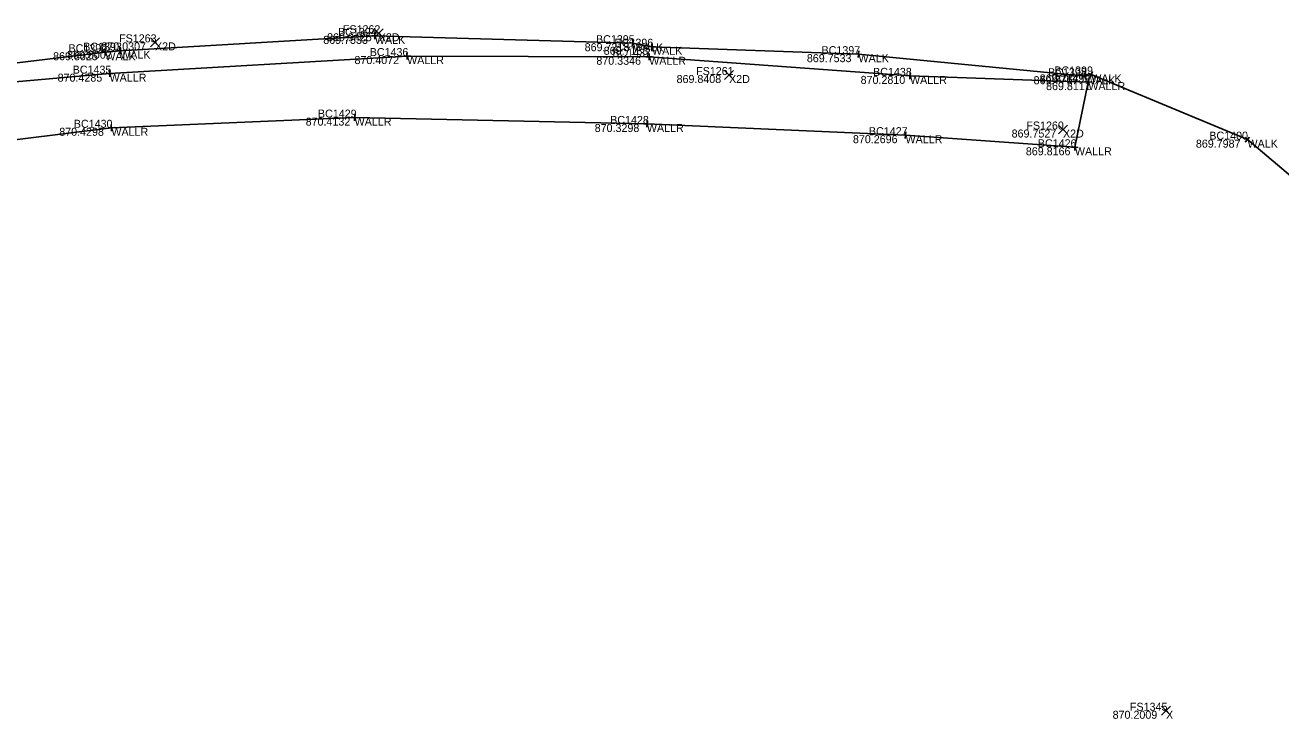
# Model space of a CAD drawing. Extents: x 1479425 to 1480294, y 379351 to 380102.
# Drawn here: x 1479629.1 to 1479638.52, y 379868.14 to 379873.34 of the extents above; entities that cross this region are included whole.
import ezdxf

# ---------------------------------------------------------------- set-up
doc = ezdxf.new("R2010")
doc.units = 0
for name, color, linetype in [('PV_X_Walk', 7, 'Continuous'), ('RD_X_Wall', 7, 'Continuous'), ('SV_X_Random_Point', 7, 'Continuous'), ('SV_X_Shot_Marker', 7, 'Continuous'), ('SV_X_Text_Comment', 7, 'Continuous'), ('SV_X_Text_Elevation', 7, 'Continuous'), ('SV_X_Text_Name', 7, 'Continuous')]:
    doc.layers.add(name, color=color, linetype=linetype)

msp = doc.modelspace()

# ---------------------------------------------------------------- linework, layer by layer
at = {"layer": 'PV_X_Walk'}
msp.add_lwpolyline([(1479639.0409, 379871.8337), (1479638.2687, 379872.4839), (1479637.0974, 379872.9725), (1479637.0508, 379872.9593), (1479635.3514, 379873.1245), (1479633.8033, 379873.1802), (1479633.6601, 379873.2067), (1479631.7248, 379873.2616), (1479629.8147, 379873.1506), (1479629.7038, 379873.1391), (1479627.9217, 379872.925), (1479625.77, 379872.5683), (1479625.6217, 379872.6102), (1479623.1104, 379872.0351)], dxfattribs=at)
at = {"layer": 'RD_X_Wall'}
msp.add_lwpolyline([(1479636.9747, 379872.4267), (1479635.7044, 379872.5174), (1479633.7647, 379872.6014), (1479631.5731, 379872.6491), (1479629.7491, 379872.5728), (1479626.9881, 379872.2291), (1479625.7759, 379872.0832), (1479625.7496, 379872.5499), (1479627.327, 379872.7681), (1479629.7353, 379872.9786), (1479631.9666, 379873.1104), (1479633.7819, 379873.105), (1479635.738, 379872.9618), (1479637.0752, 379872.9151)], close=True, dxfattribs=at)
at = {"layer": 'SV_X_Random_Point'}
for p, q in [((1479631.7207, 379873.2479), (1479631.7873, 379873.3147)), ((1479631.7207, 379873.3147), (1479631.7873, 379873.2479)), ((1479630.0427, 379873.1797), (1479630.1093, 379873.2465)), ((1479630.0427, 379873.2465), (1479630.1093, 379873.1797)), ((1479634.3477, 379872.9349), (1479634.4143, 379873.0017)), ((1479634.3477, 379873.0017), (1479634.4143, 379872.9349)), ((1479636.8517, 379872.5264), (1479636.9183, 379872.5932)), ((1479636.8517, 379872.5932), (1479636.9183, 379872.5264)), ((1479637.6247, 379868.17), (1479637.6913, 379868.2368)), ((1479637.6247, 379868.2368), (1479637.6913, 379868.17))]:
    msp.add_line(p, q, dxfattribs=at)
at = {"layer": 'SV_X_Shot_Marker'}
for p, q in [((1479631.7498, 379873.2609), (1479631.6998, 379873.2623)), ((1479631.7241, 379873.2366), (1479631.7255, 379873.2866)), ((1479631.7248, 379873.2616), (1479631.7248, 379873.2616)), ((1479633.6555, 379873.1821), (1479633.6646, 379873.2313)), ((1479629.7287, 379873.1417), (1479629.6789, 379873.1365)), ((1479629.7064, 379873.1143), (1479629.7012, 379873.164)), ((1479629.7038, 379873.1391), (1479629.7038, 379873.1391)), ((1479629.8397, 379873.1521), (1479629.7897, 379873.1492)), ((1479629.8161, 379873.1257), (1479629.8132, 379873.1756)), ((1479629.8147, 379873.1506), (1479629.8147, 379873.1506)), ((1479631.9651, 379873.1354), (1479631.9681, 379873.0855)), ((1479633.6847, 379873.2022), (1479633.6355, 379873.2113)), ((1479633.6601, 379873.2067), (1479633.6601, 379873.2067)), ((1479633.8283, 379873.1793), (1479633.7783, 379873.1811)), ((1479633.782, 379873.13), (1479633.7818, 379873.08)), ((1479633.8024, 379873.1552), (1479633.8042, 379873.2052)), ((1479633.8033, 379873.1802), (1479633.8033, 379873.1802)), ((1479635.3763, 379873.1221), (1479635.3265, 379873.1269)), ((1479635.349, 379873.0996), (1479635.3538, 379873.1494)), ((1479635.3514, 379873.1245), (1479635.3514, 379873.1245)), ((1479631.9416, 379873.1089), (1479631.9916, 379873.1119)), ((1479631.9666, 379873.1104), (1479631.9666, 379873.1104)), ((1479633.7569, 379873.1051), (1479633.8069, 379873.1049)), ((1479633.7819, 379873.105), (1479633.7819, 379873.105)), ((1479629.7104, 379872.9764), (1479629.7602, 379872.9808)), ((1479629.7331, 379873.0035), (1479629.7375, 379872.9537)), ((1479629.7353, 379872.9786), (1479629.7353, 379872.9786)), ((1479635.7131, 379872.9636), (1479635.7629, 379872.96)), ((1479635.7398, 379872.9868), (1479635.7362, 379872.9369)), ((1479635.738, 379872.9618), (1479635.738, 379872.9618)), ((1479637.0749, 379872.9661), (1479637.0267, 379872.9525)), ((1479637.0576, 379872.9353), (1479637.044, 379872.9834)), ((1479637.0508, 379872.9593), (1479637.0508, 379872.9593)), ((1479637.1205, 379872.9629), (1479637.0743, 379872.9821)), ((1479637.0761, 379872.9401), (1479637.0743, 379872.8901)), ((1479637.0878, 379872.9494), (1479637.107, 379872.9956)), ((1479637.0974, 379872.9725), (1479637.0974, 379872.9725)), ((1479637.0502, 379872.916), (1479637.1002, 379872.9142)), ((1479637.0752, 379872.9151), (1479637.0752, 379872.9151)), ((1479631.5726, 379872.6241), (1479631.5736, 379872.6741)), ((1479629.7741, 379872.5739), (1479629.7241, 379872.5718)), ((1479629.7501, 379872.5478), (1479629.7481, 379872.5978)), ((1479629.7491, 379872.5728), (1479629.7491, 379872.5728)), ((1479631.5981, 379872.6486), (1479631.5481, 379872.6497)), ((1479631.5731, 379872.6491), (1479631.5731, 379872.6491)), ((1479633.7897, 379872.6003), (1479633.7397, 379872.6025)), ((1479633.7636, 379872.5764), (1479633.7658, 379872.6264)), ((1479633.7647, 379872.6014), (1479633.7647, 379872.6014)), ((1479635.7293, 379872.5156), (1479635.6795, 379872.5192)), ((1479635.7026, 379872.4925), (1479635.7062, 379872.5424)), ((1479635.7044, 379872.5174), (1479635.7044, 379872.5174)), ((1479638.2878, 379872.4678), (1479638.2496, 379872.5)), ((1479638.2526, 379872.4648), (1479638.2848, 379872.503)), ((1479638.2687, 379872.4839), (1479638.2687, 379872.4839)), ((1479636.9996, 379872.4249), (1479636.9498, 379872.4285)), ((1479636.9729, 379872.4018), (1479636.9765, 379872.4517)), ((1479636.9747, 379872.4267), (1479636.9747, 379872.4267))]:
    msp.add_line(p, q, dxfattribs=at)

# ---------------------------------------------------------------- texts
at = {"layer": 'SV_X_Text_Comment'}
for s, p in [('WALK', (1479631.7248, 379873.2016)), ('X2D', (1479631.754, 379873.2213)), ('WALK', (1479629.7038, 379873.0791)), ('WALK', (1479629.8147, 379873.0906)), ('X2D', (1479630.076, 379873.1531)), ('WALK', (1479633.6601, 379873.1467)), ('WALK', (1479633.8033, 379873.1202)), ('WALK', (1479635.3514, 379873.0645)), ('WALLR', (1479631.9666, 379873.0504)), ('WALLR', (1479633.7819, 379873.045)), ('WALLR', (1479629.7353, 379872.9186)), ('X2D', (1479634.381, 379872.9083)), ('WALLR', (1479635.738, 379872.9018)), ('WALK', (1479637.0508, 379872.8993)), ('WALK', (1479637.0974, 379872.9125)), ('WALLR', (1479637.0752, 379872.8551)), ('WALLR', (1479629.7491, 379872.5128)), ('WALLR', (1479631.5731, 379872.5891)), ('WALLR', (1479633.7647, 379872.5414)), ('X2D', (1479636.885, 379872.4998)), ('WALLR', (1479635.7044, 379872.4574)), ('WALK', (1479638.2687, 379872.4239)), ('WALLR', (1479636.9747, 379872.3667)), ('X', (1479637.658, 379868.1434))]:
    msp.add_text(s, height=0.06, dxfattribs=at).set_placement(p)
at = {"layer": 'SV_X_Text_Elevation'}
for s, p in [('869.7533', (1479631.3379, 379873.2016)), ('869.9425', (1479631.3666, 379873.2213)), ('869.8025', (1479629.3122, 379873.0791)), ('869.8002', (1479629.4169, 379873.0906)), ('870.0307', (1479629.674, 379873.1531)), ('869.7218', (1479633.2983, 379873.1467)), ('869.7183', (1479633.441, 379873.1202)), ('869.7533', (1479634.9645, 379873.0645)), ('870.4072', (1479631.5721, 379873.0504)), ('870.3346', (1479633.386, 379873.045)), ('870.4285', (1479629.346, 379872.9186)), ('869.8408', (1479633.9875, 379872.9083)), ('870.2810', (1479635.3677, 379872.9018)), ('869.7767', (1479636.6648, 379872.8993)), ('869.7849', (1479636.7105, 379872.9125)), ('869.8111', (1479636.7582, 379872.8551)), ('870.4298', (1479629.3584, 379872.5128)), ('870.4132', (1479631.2061, 379872.5891)), ('870.3298', (1479633.3735, 379872.5414)), ('869.7527', (1479636.5, 379872.4998)), ('870.2696', (1479635.3099, 379872.4574)), ('869.7987', (1479637.8818, 379872.4239)), ('869.8166', (1479636.6067, 379872.3667)), ('870.2009', (1479637.2574, 379868.1434))]:
    msp.add_text(s, height=0.06, dxfattribs=at).set_placement(p)
at = {"layer": 'SV_X_Text_Name'}
for s, p in [('BC1394', (1479631.4485, 379873.2616)), ('FS1262', (1479631.4852, 379873.2813)), ('FS1263', (1479629.8068, 379873.2131)), ('BC1395', (1479633.3833, 379873.2067)), ('BC1396', (1479633.5227, 379873.1802)), ('BC1392', (1479629.4275, 379873.1391)), ('BC1393', (1479629.5379, 379873.1506)), ('BC1436', (1479631.6865, 379873.1104)), ('BC1437', (1479633.5056, 379873.105)), ('BC1397', (1479635.0746, 379873.1245)), ('BC1435', (1479629.459, 379872.9786)), ('FS1261', (1479634.1343, 379872.9683)), ('BC1399', (1479636.8201, 379872.9725)), ('BC1438', (1479635.4612, 379872.9618)), ('BC1398', (1479636.7735, 379872.9593)), ('BC1439', (1479636.7984, 379872.9151)), ('BC1429', (1479631.2982, 379872.6491)), ('BC1428', (1479633.4898, 379872.6014)), ('BC1430', (1479629.4676, 379872.5728)), ('BC1427', (1479635.43, 379872.5174)), ('FS1260', (1479636.6106, 379872.5598)), ('BC1426', (1479636.6965, 379872.4267)), ('BC1400', (1479637.9825, 379872.4839)), ('FS1345', (1479637.3873, 379868.2034))]:
    msp.add_text(s, height=0.06, dxfattribs=at).set_placement(p)

doc.saveas('drawing.dxf')
